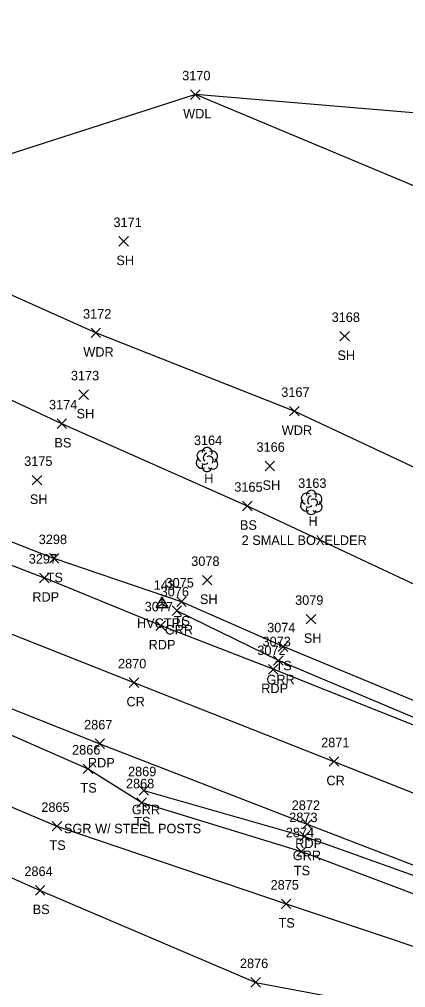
# Model space of a CAD drawing. Extents: x 1599569 to 1610055, y 642560 to 647860.
# Drawn here: x 1600349.8 to 1600431, y 647459.9 to 647663.5 of the extents above; entities that cross this region are included whole.
import ezdxf

# ---------------------------------------------------------------- set-up
doc = ezdxf.new("R2010")
doc.units = 0
for name, color, linetype in [('C_A', 7, 'Continuous'), ('C_I', 7, 'Continuous'), ('CPSM', 7, 'Continuous'), ('L_A', 7, 'Continuous'), ('L_C', 7, 'Continuous'), ('L_I', 7, 'Continuous'), ('L_TIC', 7, 'Continuous'), ('LAWA', 7, 'Continuous'), ('LELB', 7, 'Continuous'), ('LSOGP', 7, 'Continuous'), ('LTD', 7, 'Continuous'), ('P_A', 7, 'Continuous'), ('P_I', 7, 'Continuous'), ('P_TIC', 7, 'Continuous'), ('PET', 7, 'Continuous'), ('PRC', 7, 'Continuous'), ('R_A', 7, 'Continuous'), ('R_C', 7, 'Continuous'), ('R_I', 7, 'Continuous'), ('R_TIC', 7, 'Continuous'), ('RGR', 7, 'Continuous')]:
    doc.layers.add(name, color=color, linetype=linetype)

msp = doc.modelspace()

# ---------------------------------------------------------------- linework, layer by layer
at = {"layer": 'CPSM'}
for p, q in [((1600378.55, 647539.81), (1600379.8, 647541.98)), ((1600381.05, 647539.81), (1600379.8, 647541.98)), ((1600379.8, 647540.53), (1600379.8, 647541.98)), ((1600378.55, 647539.81), (1600379.8, 647540.53)), ((1600378.55, 647539.81), (1600381.05, 647539.81)), ((1600379.8, 647540.53), (1600379.8, 647540.53)), ((1600379.8, 647540.53), (1600381.05, 647539.81))]:
    msp.add_line(p, q, dxfattribs=at)
at = {"layer": 'L_TIC'}
for points in [[(1600385.77, 647646.65), (1600387.77, 647648.65)], [(1600387.77, 647646.65), (1600385.77, 647648.65)], [(1600370.67, 647615.8), (1600372.67, 647617.8)], [(1600372.67, 647615.8), (1600370.67, 647617.8)], [(1600364.84, 647596.55), (1600366.84, 647598.55)], [(1600366.84, 647596.55), (1600364.84, 647598.55)], [(1600417.15, 647595.85), (1600419.15, 647597.85)], [(1600419.15, 647595.85), (1600417.15, 647597.85)], [(1600362.29, 647583.57), (1600364.29, 647585.57)], [(1600364.29, 647583.57), (1600362.29, 647585.57)], [(1600406.56, 647580.09), (1600408.56, 647582.09)], [(1600408.56, 647580.09), (1600406.56, 647582.09)], [(1600357.68, 647577.46), (1600359.68, 647579.46)], [(1600359.68, 647577.46), (1600357.68, 647579.46)], [(1600401.41, 647568.55), (1600403.41, 647570.55)], [(1600403.41, 647568.55), (1600401.41, 647570.55)], [(1600352.47, 647565.58), (1600354.47, 647567.58)], [(1600354.47, 647565.58), (1600352.47, 647567.58)], [(1600396.69, 647560.15), (1600398.69, 647562.15)], [(1600398.69, 647560.15), (1600396.69, 647562.15)], [(1600356.09, 647549.14), (1600358.09, 647551.14)], [(1600358.09, 647549.14), (1600356.09, 647551.14)], [(1600356.09, 647549.14), (1600358.09, 647551.14)], [(1600358.09, 647549.14), (1600356.09, 647551.14)], [(1600388.23, 647544.55), (1600390.23, 647546.55)], [(1600390.23, 647544.55), (1600388.23, 647546.55)], [(1600382.83, 647540.02), (1600384.83, 647542.02)], [(1600384.83, 647540.02), (1600382.83, 647542.02)], [(1600410.08, 647536.37), (1600412.08, 647538.37)], [(1600412.08, 647536.37), (1600410.08, 647538.37)], [(1600404.19, 647530.59), (1600406.19, 647532.59)], [(1600406.19, 647530.59), (1600404.19, 647532.59)], [(1600363.2, 647504.89), (1600365.2, 647506.89)], [(1600365.2, 647504.89), (1600363.2, 647506.89)], [(1600374.48, 647497.79), (1600376.48, 647499.79)], [(1600376.48, 647497.79), (1600374.48, 647499.79)], [(1600356.67, 647492.84), (1600358.67, 647494.84)], [(1600358.67, 647492.84), (1600356.67, 647494.84)], [(1600408.04, 647487.5), (1600410.04, 647489.5)], [(1600410.04, 647487.5), (1600408.04, 647489.5)], [(1600353.12, 647479.34), (1600355.12, 647481.34)], [(1600355.12, 647479.34), (1600353.12, 647481.34)], [(1600404.84, 647476.5), (1600406.84, 647478.5)], [(1600406.84, 647476.5), (1600404.84, 647478.5)], [(1600398.45, 647459.99), (1600400.45, 647461.99)], [(1600400.45, 647459.99), (1600398.45, 647461.99)]]:
    msp.add_lwpolyline(points, dxfattribs=at)
at = {"layer": 'LAWA'}
for points in [[(1600737.44, 647480.52), (1600749.33, 647467.35), (1600730, 647462.77), (1600685.34, 647477.97), (1600643.61, 647489.56), (1600602.74, 647501.99), (1600542.89, 647519.56), (1600513.51, 647532.8), (1600459.11, 647556.92), (1600407.56, 647581.09), (1600365.84, 647597.55), (1600328.36, 647614.3), (1600286.9, 647630.81), (1600248.27, 647645.58), (1600208.97, 647660.75), (1600170.58, 647674.95), (1600134.14, 647689.04), (1600090.43, 647707.15), (1600050.9, 647710.69), (1600009.49, 647721.85), (1599974.8, 647749.03), (1599978.26, 647757.91)], [(1600737.44, 647480.52), (1600693.85, 647507.84), (1600659.23, 647522.02), (1600616.59, 647547.15), (1600572.91, 647566.58), (1600531.29, 647582.2), (1600493.06, 647599.22), (1600436.17, 647627), (1600386.77, 647647.65)]]:
    msp.add_lwpolyline(points, dxfattribs=at)
at = {"layer": 'LELB'}
for points in [[(1599728.81, 647812.31), (1599768.15, 647792.96), (1599808.19, 647772.58), (1599853.49, 647751.31), (1599896.91, 647732.66), (1599944.27, 647711.3), (1599995.07, 647690.25), (1600038.53, 647673.11), (1600069.53, 647660.63), (1600111.66, 647644.91), (1600147.02, 647631.01), (1600185.01, 647616.1), (1600232.31, 647597.96), (1600265.15, 647585.19), (1600308.36, 647569.24), (1600357.09, 647550.14)], [(1600537.7, 647496.6), (1600505.24, 647508.6), (1600447.9, 647537.54), (1600397.69, 647561.15), (1600358.68, 647578.46), (1600320.54, 647596.22), (1600277.06, 647612.23), (1600242.57, 647623.27), (1600200.08, 647639.28), (1600158.58, 647653.74), (1600122.27, 647670.33), (1600079.68, 647685.7), (1600046.48, 647697.09), (1600008.61, 647711.28), (1599963.43, 647729.15), (1599915.25, 647747.24), (1599888.72, 647769.57)], [(1599697.61, 647759.98), (1599722.1, 647751.43), (1599744.36, 647752.34), (1599789.18, 647723.21), (1599824.42, 647706.1), (1599868.39, 647681.04), (1599912.82, 647658.19), (1599958.42, 647634.17), (1599997.43, 647618.28), (1600043.89, 647603.78), (1600086.31, 647587.76), (1600138.43, 647576.08), (1600182.57, 647557.27), (1600228.03, 647536.75), (1600266.38, 647516.33), (1600313.23, 647498.51), (1600354.12, 647480.34), (1600399.45, 647460.99), (1600449.42, 647451.6), (1600497.01, 647440.19)], [(1600055.84, 647629.73), (1600100.47, 647612.9), (1600146.77, 647594.54), (1600189.82, 647577.13), (1600237.92, 647558.86), (1600277.02, 647541.96), (1600322.78, 647524.01), (1600364.2, 647505.89), (1600375.48, 647498.79), (1600409.04, 647488.5), (1600456.88, 647470.52), (1600501.29, 647454.21), (1600533.9, 647440.09), (1600569.02, 647426.96), (1600611.34, 647410.57), (1600650.69, 647394.91), (1600690.03, 647379.36), (1600728.9, 647364.07), (1600769.48, 647348.66), (1600809.53, 647333.88)], [(1600091.96, 647601.56), (1600141.36, 647582.29), (1600184.89, 647565.22), (1600231.4, 647544.86), (1600270.58, 647527.32), (1600317.56, 647510.77), (1600357.67, 647493.84), (1600405.84, 647477.5), (1600453.75, 647461.49)], [(1601065.14, 647298.7), (1601017.93, 647308.63), (1600970.12, 647319.08), (1600922.99, 647332.86), (1600876.04, 647347.67), (1600828.44, 647364.9), (1600781.51, 647382.96), (1600734.1, 647401.33), (1600686.53, 647420.21), (1600637.49, 647439.52), (1600589.75, 647457.41), (1600542.23, 647476.94), (1600495.72, 647495.2), (1600449.86, 647513.12), (1600405.19, 647531.59), (1600383.83, 647541.02), (1600357.09, 647550.14)]]:
    msp.add_lwpolyline(points, dxfattribs=at)
at = {"layer": 'LSOGP'}
msp.add_lwpolyline([(1600824.54, 647496.94), (1600763.73, 647518.52), (1600720.23, 647538.15), (1600674.33, 647558.6), (1600630.97, 647577.79), (1600579.41, 647601.35), (1600532.57, 647622.07), (1600481.31, 647645.17), (1600444.94, 647660.58), (1600444.02, 647658.36), (1600438.96, 647650.21), (1600437.92, 647647.06), (1600435.87, 647643.54), (1600386.78, 647647.65), (1600336.85, 647631.6), (1600286.9, 647630.81), (1600248.28, 647645.58), (1600208.97, 647660.74), (1600170.58, 647674.94), (1600134.14, 647689.04), (1600090.44, 647707.15), (1600057.63, 647725.77)], dxfattribs=at)
at = {"layer": 'LTD'}
for p, q in [((1600389.19, 647570.96), (1600389.19, 647570.96)), ((1600389.19, 647570.96), (1600389.19, 647570.96)), ((1600411.11, 647561.96), (1600411.11, 647561.96)), ((1600411.11, 647561.96), (1600411.11, 647561.96))]:
    msp.add_line(p, q, dxfattribs=at)
for centre in [(1600389.23, 647572.39), (1600411.15, 647563.4)]:
    msp.add_arc(centre, 1.05, 335.5272, 180.9563, dxfattribs=at)
for centre, major_axis, ratio, start_param, end_param in [((1600388.39, 647571.63), (1.21, -0.51), 0.895232, 1.570796, 4.712389), ((1600388.98, 647571.42), (-0.208, -0.792), 0.645439, 3.141593, 6.283185), ((1600390.23, 647571.54), (-1.14, -0.48), 0.949671, 1.570796, 4.712389), ((1600388.1, 647570.25), (0.58, -1.04), 0.959034, 3.141593, 6.283185), ((1600388.73, 647570.21), (-0.625, -0.083), 0.423636, 0, 3.141593), ((1600389.69, 647570.79), (-0.5, 0.667), 0.989748, 3.141593, 6.283185), ((1600390.19, 647570.13), (-1.09, 0.79), 0.841452, 1.570796, 4.712389), ((1600389.19, 647569.46), (0.26, 1.06), 0.942809, 1.570796, 4.712389), ((1600410.32, 647562.63), (1.21, -0.51), 0.895232, 1.570796, 4.712389), ((1600412.15, 647562.55), (-1.14, -0.48), 0.949671, 1.570796, 4.712389), ((1600410.02, 647561.26), (0.58, -1.04), 0.959034, 3.141593, 6.283185), ((1600410.9, 647562.42), (-0.208, -0.792), 0.645439, 3.141593, 6.283185), ((1600411.61, 647561.8), (-0.5, 0.667), 0.989748, 3.141593, 6.283185), ((1600412.11, 647561.13), (-1.09, 0.79), 0.841452, 1.570796, 4.712389), ((1600411.11, 647560.46), (0.26, 1.06), 0.942809, 1.570796, 4.712389), ((1600410.65, 647561.21), (-0.625, -0.083), 0.423636, 0, 3.141593)]:
    msp.add_ellipse(centre, major_axis=major_axis, ratio=ratio, start_param=start_param, end_param=end_param, dxfattribs=at)
at = {"layer": 'P_TIC'}
for points in [[(1600353.99, 647545.03), (1600355.99, 647547.03)], [(1600355.99, 647545.03), (1600353.99, 647547.03)], [(1600353.99, 647545.03), (1600355.99, 647547.03)], [(1600355.99, 647545.03), (1600353.99, 647547.03)], [(1600378.45, 647535), (1600380.45, 647537)], [(1600380.45, 647535), (1600378.45, 647537)], [(1600402.13, 647525.81), (1600404.13, 647527.81)], [(1600404.13, 647525.81), (1600402.13, 647527.81)], [(1600372.85, 647523.01), (1600374.85, 647525.01)], [(1600374.85, 647523.01), (1600372.85, 647525.01)], [(1600365.68, 647510.17), (1600367.68, 647512.17)], [(1600367.68, 647510.17), (1600365.68, 647512.17)], [(1600414.89, 647506.43), (1600416.89, 647508.43)], [(1600416.89, 647506.43), (1600414.89, 647508.43)], [(1600409.28, 647493.24), (1600411.28, 647495.24)], [(1600411.28, 647493.24), (1600409.28, 647495.24)]]:
    msp.add_lwpolyline(points, dxfattribs=at)
at = {"layer": 'PET'}
for points in [[(1599726.38, 647809.62), (1599765.17, 647788.95), (1599807.03, 647767.98), (1599850.85, 647747.24), (1599895.21, 647727.77), (1599941.94, 647707.82), (1599994.49, 647686.81), (1600037.05, 647669.82), (1600068.7, 647657.7), (1600109.97, 647641.43), (1600146.07, 647627.29), (1600183.44, 647612.79), (1600231.32, 647594.52), (1600263.07, 647581.81), (1600307.68, 647564.32), (1600354.99, 647546.03)], [(1600057, 647632.55), (1600100.87, 647615.07), (1600147.9, 647596.67), (1600191.15, 647579.83), (1600239.1, 647561.25), (1600278.32, 647545.78), (1600324.18, 647528.07), (1600366.68, 647511.17), (1600410.28, 647494.24), (1600458.68, 647475.59), (1600502.98, 647458.78), (1600537.74, 647444.52), (1600578.73, 647428.32), (1600625.87, 647410.05), (1600676.47, 647390.02), (1600722.37, 647372.09), (1600742.13, 647364.34), (1600771.17, 647353.24), (1600818.96, 647335.1)], [(1600827.68, 647360.8), (1600779.98, 647378.97), (1600733.01, 647397.03), (1600684.81, 647415.39), (1600635.75, 647434.82), (1600588.71, 647453.36), (1600540.53, 647472.21), (1600493.83, 647490.9), (1600448.1, 647508.92), (1600403.13, 647526.81), (1600379.45, 647536), (1600354.99, 647546.03)]]:
    msp.add_lwpolyline(points, dxfattribs=at)
at = {"layer": 'PRC'}
msp.add_lwpolyline([(1600061.65, 647646.14), (1600106.08, 647628.64), (1600153.61, 647610.06), (1600197.14, 647593.63), (1600244.86, 647574.99), (1600283.53, 647559.51), (1600330.13, 647541.37), (1600373.85, 647524.01), (1600415.89, 647507.43), (1600464.39, 647488.21), (1600507.95, 647471.08), (1600542.28, 647457.18), (1600583.6, 647441.31), (1600630.18, 647422.59), (1600680.85, 647402.94), (1600728.14, 647384.11), (1600746.62, 647376.72), (1600776.73, 647364.8), (1600822.54, 647348.05)], dxfattribs=at)
at = {"layer": 'R_TIC'}
for points in [[(1600381.85, 647538.14), (1600383.85, 647540.14)], [(1600383.85, 647538.14), (1600381.85, 647540.14)], [(1600403.22, 647527.66), (1600405.22, 647529.66)], [(1600405.22, 647527.66), (1600403.22, 647529.66)], [(1600374.92, 647500.33), (1600376.92, 647502.33)], [(1600376.92, 647500.33), (1600374.92, 647502.33)], [(1600408.75, 647490.68), (1600410.75, 647492.68)], [(1600410.75, 647490.68), (1600408.75, 647492.68)]]:
    msp.add_lwpolyline(points, dxfattribs=at)
at = {"layer": 'RGR'}
for points in [[(1601112.7, 647287.9), (1601065.04, 647296.19), (1601016.91, 647305.01), (1600969.35, 647316.03), (1600921.82, 647329.78), (1600875.51, 647344.39), (1600827.81, 647361.39), (1600780.14, 647379.57), (1600733.34, 647397.57), (1600685.04, 647416.17), (1600636.13, 647435.4), (1600589.04, 647454.23), (1600540.52, 647473.18), (1600494.45, 647491.58), (1600448.44, 647509.99), (1600404.22, 647528.66), (1600382.85, 647539.14)], [(1600375.92, 647501.33), (1600409.75, 647491.68), (1600457.98, 647474.45), (1600502.92, 647457.62), (1600537.28, 647443.8), (1600578.29, 647427.64), (1600625.5, 647409.22), (1600676.4, 647389.23), (1600721.9, 647371.23), (1600741.51, 647363.43), (1600770.59, 647352.25), (1600818.71, 647334.42), (1600868.72, 647316.7), (1600918.16, 647301.27), (1600965.58, 647287.14), (1601011.99, 647275.75), (1601059.57, 647265), (1601100.83, 647257.3), (1601109.97, 647255.84)]]:
    msp.add_lwpolyline(points, dxfattribs=at)

# ---------------------------------------------------------------- texts
at = {"layer": 'C_A'}
msp.add_text('HVCTRL', height=2, dxfattribs=at).set_placement((1600374.49, 647535.53))
at = {"layer": 'C_I'}
msp.add_text('143', height=2, dxfattribs=at).set_placement((1600378, 647543.53))
at = {"layer": 'L_A'}
for s, p in [('WDL', (1600384.19, 647642.65)), ('SH', (1600370.16, 647611.8)), ('WDR', (1600363.2, 647592.55)), ('SH', (1600416.63, 647591.85)), ('SH', (1600361.78, 647579.57)), ('WDR', (1600404.92, 647576.09)), ('BS', (1600357.13, 647573.46)), ('H', (1600388.62, 647565.96)), ('SH', (1600400.89, 647564.55)), ('SH', (1600351.96, 647561.58)), ('BS', (1600396.13, 647556.15)), ('H', (1600410.54, 647556.96)), ('TS', (1600355.5, 647545.14)), ('TS', (1600355.5, 647545.14)), ('SH', (1600387.72, 647540.55)), ('TS', (1600382.23, 647536.02)), ('SH', (1600409.57, 647532.37)), ('TS', (1600403.6, 647526.59)), ('TS', (1600362.61, 647500.89)), ('TS', (1600373.89, 647493.79)), ('TS', (1600356.08, 647488.84)), ('TS', (1600407.45, 647483.5)), ('BS', (1600352.56, 647475.34)), ('TS', (1600404.25, 647472.5))]:
    msp.add_text(s, height=2, dxfattribs=at).set_placement(p)
at = {"layer": 'L_C'}
msp.add_text('2 SMALL BOXELDER', height=2, dxfattribs=at).set_placement((1600396.49, 647552.96))
at = {"layer": 'L_I'}
for s, p in [('3170', (1600383.99, 647650.65)), ('3171', (1600369.54, 647619.8)), ('3172', (1600363.14, 647600.55)), ('3168', (1600415.41, 647599.85)), ('3173', (1600360.59, 647587.57)), ('3167', (1600404.82, 647584.09)), ('3174', (1600355.99, 647581.46)), ('3164', (1600386.45, 647573.96)), ('3166', (1600399.61, 647572.55)), ('3175', (1600350.77, 647569.58)), ('3165', (1600394.95, 647564.15)), ('3163', (1600408.37, 647564.96)), ('3298', (1600353.83, 647553.14)), ('3298', (1600353.83, 647553.14)), ('3078', (1600385.89, 647548.55)), ('3075', (1600380.49, 647544.02)), ('3079', (1600407.73, 647540.37)), ('3074', (1600401.85, 647534.59)), ('2866', (1600360.84, 647508.89)), ('2868', (1600372.17, 647501.79)), ('2865', (1600354.37, 647496.84)), ('2874', (1600405.78, 647491.5)), ('2864', (1600350.81, 647483.34)), ('2875', (1600402.58, 647480.5)), ('2876', (1600396.13, 647463.99))]:
    msp.add_text(s, height=2, dxfattribs=at).set_placement(p)
at = {"layer": 'P_A'}
for s, p in [('RDP', (1600352.48, 647541.03)), ('RDP', (1600352.48, 647541.03)), ('RDP', (1600376.93, 647531)), ('RDP', (1600400.61, 647521.81)), ('CR', (1600372.28, 647519.01)), ('RDP', (1600364.17, 647506.17)), ('CR', (1600414.32, 647502.43)), ('RDP', (1600407.76, 647489.24))]:
    msp.add_text(s, height=2, dxfattribs=at).set_placement(p)
at = {"layer": 'P_I'}
for s, p in [('3297', (1600351.73, 647549.03)), ('3297', (1600351.73, 647549.03)), ('3077', (1600376.11, 647539)), ('3072', (1600399.79, 647529.81)), ('2870', (1600370.5, 647527.01)), ('2867', (1600363.37, 647514.17)), ('2871', (1600413.2, 647510.43)), ('2872', (1600407.02, 647497.24))]:
    msp.add_text(s, height=2, dxfattribs=at).set_placement(p)
at = {"layer": 'R_A'}
for p in [(1600380.34, 647534.14), (1600401.71, 647523.66), (1600373.4, 647496.33), (1600407.24, 647486.68)]:
    msp.add_text('GRR', height=2, dxfattribs=at).set_placement(p)
at = {"layer": 'R_C'}
msp.add_text('SGR W/ STEEL POSTS', height=2, dxfattribs=at).set_placement((1600359.14, 647492.33))
at = {"layer": 'R_I'}
for s, p in [('3076', (1600379.46, 647542.14)), ('3073', (1600400.88, 647531.66)), ('2869', (1600372.6, 647504.33)), ('2873', (1600406.49, 647494.68))]:
    msp.add_text(s, height=2, dxfattribs=at).set_placement(p)

doc.saveas('drawing.dxf')
